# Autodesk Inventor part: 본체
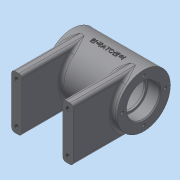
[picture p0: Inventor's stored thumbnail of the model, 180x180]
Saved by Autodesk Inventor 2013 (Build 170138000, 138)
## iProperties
Created: 2020-07
Part Number: 본체
Material: 일반
Document SubType Name: Modeling
Designer: dgall
Density: 1 g/cm^3
Mass: 113.055 g
Surface Area: 357.567 cm^2
Volume: 113.055 cm^3
Author: dgall
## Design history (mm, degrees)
sketch "스케치1"
  geometry: L1 (-35, 0)-(35, 0); L2 (-35, 0)-(-35, 26); L3 (35, 0)-(35, 26); L4 (35, 26)-(-35, 26); L5 (-35, 16)-(-23.3, 16); L6 (-23, 15.7)-(-23, 14); L7 (-23, 14)-(-21, 14); L8 (-21, 14)-(-21, 18); L9 (-18, 21)-(18, 21); L10 (21, 18)-(21, 14); L11 (21, 14)-(23, 14); L12 (23, 14)-(23, 15.7); L13 (23.3, 16)-(35, 16); A1 r 3 centre (-18, 18) between (-18, 21) and (-21, 18); A2 r 3 centre (18, 18) between (21, 18) and (18, 21); A3 r 0.3 centre (23.3, 15.7) between (23.3, 16) and (23, 15.7); A4 r 0.3 centre (-23.3, 15.7) between (-23, 15.7) and (-23.3, 16); 7 further points
  constraints: 26 end point, 10 point on line, 8 point on circle, 8 tangent, 5 parallel, 5 perpendicular, 4 centre point, 3 collinear, 2 coincident, 2 equal radius, 2 horizontal, 2 horizontal alignment, 2 midpoint
  dimensions: "d0" = 26 distance between parallel lines of L1 L4; "d2" = 21 distance between parallel lines of L1 L9; "d3" = 12 distance of point (23, 16) L13.end; "d4" = 14 distance between parallel lines of L1 L7; "d5" = 70 distance between parallel lines of L3 L2; "d6" = 42 distance of point (-21, 21) point (21, 21); "d7" = 16 distance between parallel lines of L1 L13; "d8" = 3 radius of A1; "d9" = 0.3 radius of A3
revolve "회전1" sketch "스케치1" stored, may be unused: angle "d10" = 90 deg
node "작업 평면1"
sketch "스케치2"
  geometry: L1 (35, 26)-(-35, 26) reference; L2 (35, -26)-(-35, -26) reference; L3 (-30, 26)-(-20, 26); L4 (-20, 26)-(-20, -26); L5 (-20, -26)-(-30, -26); L6 (-30, -26)-(-30, 26); L7 (20, 26)-(30, 26); L8 (30, 26)-(30, -26); L9 (30, -26)-(20, -26); L10 (20, -26)-(20, 26); 1 further point
  constraints: 16 end point, 4 parallel, 4 point on line, 2 horizontal, 2 perpendicular
  dimensions: "d12" = 60 distance between parallel lines of L8 L6; "d14" = 10 distance between parallel lines of L4 L6; "d15" = 10 distance between parallel lines of L10 L8; "d16" = 30 distance from line of L8 point (0, 0)
extrude "돌출1" join sketch "스케치2" stored distance "d17" = 10; taper "d18" = 0 deg
sketch "스케치3"
  geometry: L1 (20, 26)-(30, 26) reference; 3 further points
  constraints: 1 midpoint, 1 vertical alignment
  dimensions: "d19" = 20 vertical distance of point (0, 0) point (25, 20)
hole "구멍1" sketch "스케치3" at (25, 20) diameter "d20" = 4.134; stored, may be unused: countersink angle "d24" = 90 deg, drill point angle "d26" = 118 deg; dims "d21" = 8, "d22" = 4, "d23" = 2, "d25" = 10
fillet "모깎기1" dims "d27" = 3
node "작업 평면2"
sketch "스케치4"
  geometry: C1 r 5 at (0, 0); 1 further point
  constraints: 1 centre point, 1 coincident
  dimensions: "d29" = 10 diameter of C1
extrude "돌출2" join sketch "스케치4" stored distance "d31" = 10; taper "d32" = 0 deg
hole "구멍2" diameter "d35" = 5.188; stored, may be unused: countersink angle "d39" = 90 deg, drill point angle "d41" = 118 deg; dims "d33" = 10, "d34" = 10, "d36" = 8, "d37" = 4, "d38" = 2, "d40" = 10
sketch "스케치5"
  geometry: C1 r 26 at (0, 0) reference; 1 further point
  constraints: 1 vertical alignment
  dimensions: "d42" = 21 distance of C1.centre point (0, 21)
hole "구멍3" sketch "스케치5" at (0, 21) diameter "d43" = 3.242; stored, may be unused: countersink angle "d47" = 90 deg, drill point angle "d49" = 118 deg; dims "d44" = 8, "d45" = 4, "d46" = 2, "d48" = 10
node "작업 평면3"
sketch "스케치6"
  geometry: L1 (-35, -26)-(-35, 26) reference; 2 further points
  constraints: 1 other
  dimensions: "d54" = 35 distance from line of point (0, 0) L1; "d55" = 26 vertical distance of L1.end point (0, 0)
feature "엠보싱1" sketch "스케치6" dims "d0" = 26, "d2" = 21, "d3" = 12, "d4" = 14, "d5" = 70, "d6" = 42, "d7" = 16, "d8" = 3, "d9" = 0.3, "d56" = 0.5, "d57" = 0
chamfer "모따기1" distance "d58" = 1; stored, may be unused: second distance "d59" = 2, angle "d60" = 45 deg
fillet "모깎기2" dims "d61" = 3
fillet "모깎기3" dims "d62" = 2
sketch "스케치7"
  geometry: L1 (0, 0)-(-14.155, 0); L2 (0, 0)-(-27.251, -9.919)
  constraints: 4 end point, 1 horizontal
  dimensions: "d63" = 20 deg angle of L2 L1
node "작업 평면4"
sketch "스케치8"
  geometry: C1 r 6 at (0, 0); 1 further point
  constraints: 1 centre point, 1 coincident
  dimensions: "d64" = 12 diameter of C1
extrude "돌출3" join sketch "스케치8" stored distance "d66" = 10; taper "d67" = 0 deg
hole "구멍4" diameter "d70" = 5.188; stored, may be unused: countersink angle "d74" = 90 deg, drill point angle "d76" = 118 deg; dims "d68" = 10, "d69" = 10, "d71" = 8, "d72" = 4, "d73" = 2, "d75" = 10
fillet "모깎기4" dims "d77" = 2
node "솔리드1"
mirror "대칭1"
mirror "대칭2"
pattern_circular "원형 패턴1" dims angle "d51" = 360 deg
mirror "대칭3"
other parameters: "d11" = -64, "d28" = 29, "d53" = 26
